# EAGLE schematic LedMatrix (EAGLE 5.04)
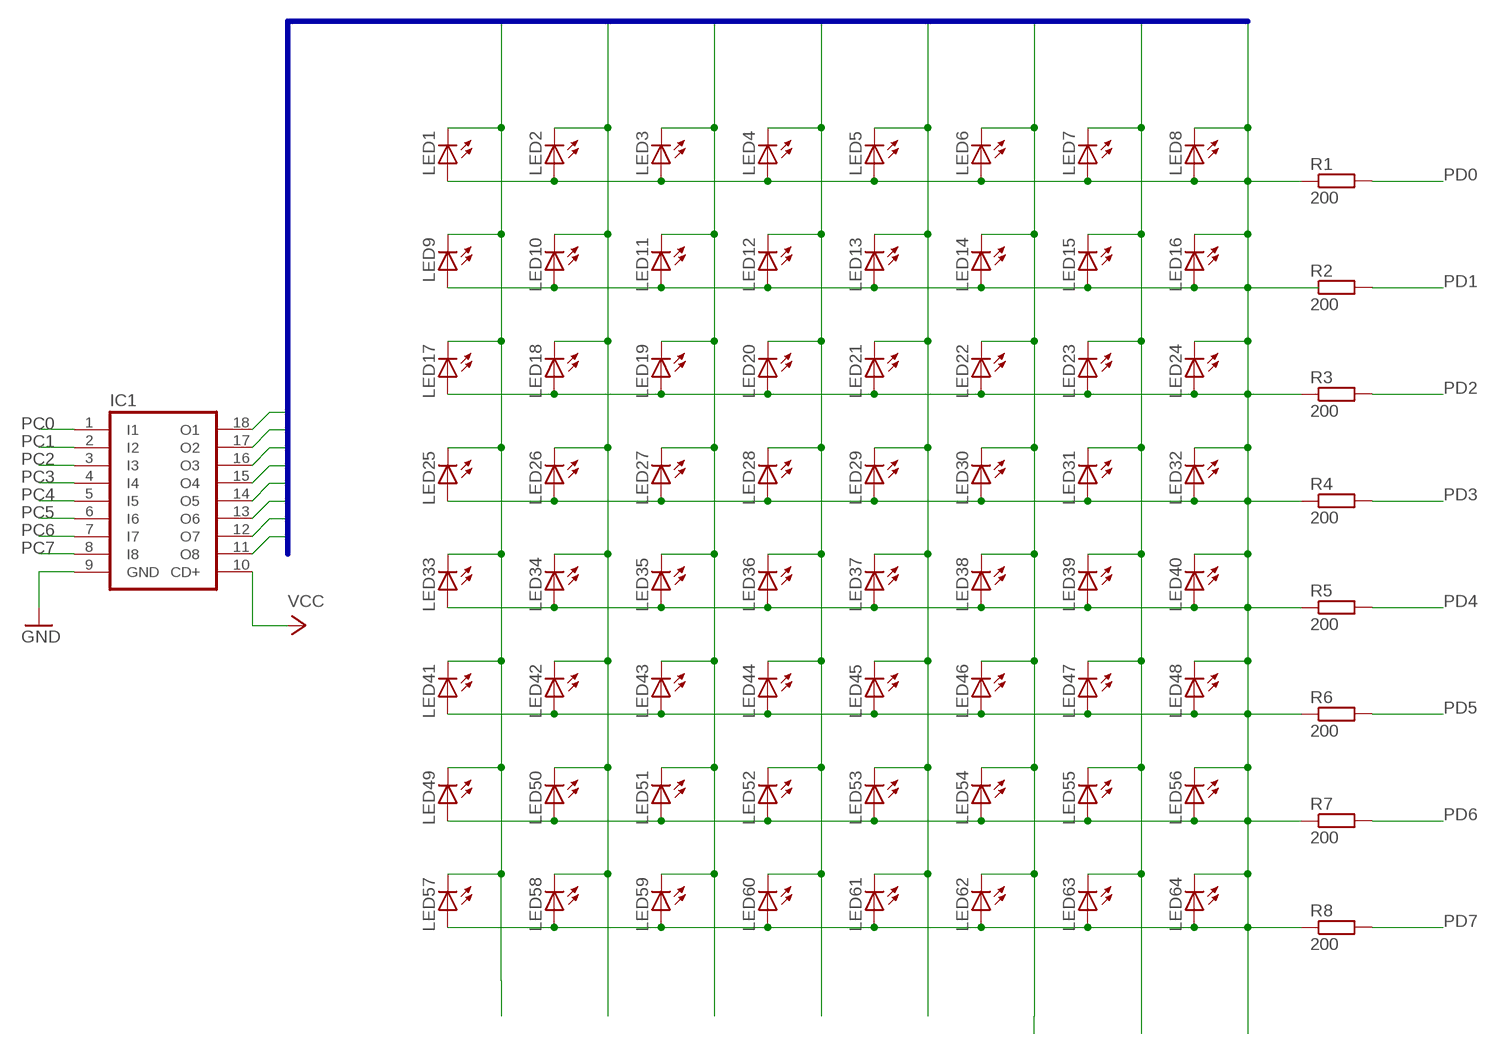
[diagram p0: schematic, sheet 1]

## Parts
IC1  ULN2804A  [DIL18]
LED1  LED  [SMARTLED-TTW]
LED2  LED  [SMARTLED-TTW]
LED3  LED  [SMARTLED-TTW]
LED4  LED  [SMARTLED-TTW]
LED5  LED  [SMARTLED-TTW]
LED6  LED  [SMARTLED-TTW]
LED7  LED  [SMARTLED-TTW]
LED8  LED  [SMARTLED-TTW]
LED9  LED  [SMARTLED-TTW]
LED10  LED  [SMARTLED-TTW]
LED11  LED  [SMARTLED-TTW]
LED12  LED  [SMARTLED-TTW]
LED13  LED  [SMARTLED-TTW]
LED14  LED  [SMARTLED-TTW]
LED15  LED  [SMARTLED-TTW]
LED16  LED  [SMARTLED-TTW]
LED17  LED  [SMARTLED-TTW]
LED18  LED  [SMARTLED-TTW]
LED19  LED  [SMARTLED-TTW]
LED20  LED  [SMARTLED-TTW]
LED21  LED  [SMARTLED-TTW]
LED22  LED  [SMARTLED-TTW]
LED23  LED  [SMARTLED-TTW]
LED24  LED  [SMARTLED-TTW]
LED25  LED  [SMARTLED-TTW]
LED26  LED  [SMARTLED-TTW]
LED27  LED  [SMARTLED-TTW]
LED28  LED  [SMARTLED-TTW]
LED29  LED  [SMARTLED-TTW]
LED30  LED  [SMARTLED-TTW]
LED31  LED  [SMARTLED-TTW]
LED32  LED  [SMARTLED-TTW]
LED33  LED  [SMARTLED-TTW]
LED34  LED  [SMARTLED-TTW]
LED35  LED  [SMARTLED-TTW]
LED36  LED  [SMARTLED-TTW]
LED37  LED  [SMARTLED-TTW]
LED38  LED  [SMARTLED-TTW]
LED39  LED  [SMARTLED-TTW]
LED40  LED  [SMARTLED-TTW]
LED41  LED  [SMARTLED-TTW]
LED42  LED  [SMARTLED-TTW]
LED43  LED  [SMARTLED-TTW]
LED44  LED  [SMARTLED-TTW]
LED45  LED  [SMARTLED-TTW]
LED46  LED  [SMARTLED-TTW]
LED47  LED  [SMARTLED-TTW]
LED48  LED  [SMARTLED-TTW]
LED49  LED  [SMARTLED-TTW]
LED50  LED  [SMARTLED-TTW]
LED51  LED  [SMARTLED-TTW]
LED52  LED  [SMARTLED-TTW]
LED53  LED  [SMARTLED-TTW]
LED54  LED  [SMARTLED-TTW]
LED55  LED  [SMARTLED-TTW]
LED56  LED  [SMARTLED-TTW]
LED57  LED  [SMARTLED-TTW]
LED58  LED  [SMARTLED-TTW]
LED59  LED  [SMARTLED-TTW]
LED60  LED  [SMARTLED-TTW]
LED61  LED  [SMARTLED-TTW]
LED62  LED  [SMARTLED-TTW]
LED63  LED  [SMARTLED-TTW]
LED64  LED  [SMARTLED-TTW]
R1  200  R-EU_0204/5  [0204/5]
R2  200  R-EU_0204/5  [0204/5]
R3  200  R-EU_0204/5  [0204/5]
R4  200  R-EU_0204/5  [0204/5]
R5  200  R-EU_0204/5  [0204/5]
R6  200  R-EU_0204/5  [0204/5]
R7  200  R-EU_0204/5  [0204/5]
R8  200  R-EU_0204/5  [0204/5]

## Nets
B$1: IC1.11(O8) IC1.12(O7) IC1.13(O6) IC1.14(O5) IC1.15(O4) IC1.16(O3) IC1.17(O2) IC1.18(O1) LED1.C@1(C) LED9.C@1(C) LED17.C@1(C) LED25.C@1(C)
GND: IC1.9(GND)
N$1: LED1.A@1(A) LED2.A@1(A) LED3.A@1(A) LED4.A@1(A) LED5.A@1(A) LED6.A@1(A) LED7.A@1(A) LED8.A@1(A) LED8.C@1(C) LED9.A@1(A) LED10.A@1(A) LED11.A@1(A) LED12.A@1(A) LED13.A@1(A) LED14.A@1(A) LED15.A@1(A) LED16.A@1(A) LED16.C@1(C) LED17.A@1(A) LED18.A@1(A) LED19.A@1(A) LED20.A@1(A) LED21.A@1(A) LED22.A@1(A) LED23.A@1(A) LED24.A@1(A) LED24.C@1(C) LED32.C@1(C) R1.1 R3.1
N$6: LED2.C@1(C) LED10.C@1(C) LED18.C@1(C) LED26.C@1(C)
N$7: LED3.C@1(C) LED11.C@1(C) LED19.C@1(C) LED27.C@1(C)
N$8: LED4.C@1(C) LED12.C@1(C) LED20.C@1(C) LED28.C@1(C)
N$9: LED5.C@1(C) LED13.C@1(C) LED21.C@1(C) LED29.C@1(C)
N$10: LED6.C@1(C) LED14.C@1(C) LED22.C@1(C) LED30.C@1(C)
N$11: LED7.C@1(C) LED15.C@1(C) LED23.C@1(C) LED31.C@1(C)
N$13: LED25.A@1(A) LED26.A@1(A) LED27.A@1(A) LED28.A@1(A) LED29.A@1(A) LED30.A@1(A) LED31.A@1(A) LED32.A@1(A) LED33.A@1(A) LED34.A@1(A) LED35.A@1(A) LED36.A@1(A) LED37.A@1(A) LED38.A@1(A) LED39.A@1(A) LED40.A@1(A) LED40.C@1(C) LED41.A@1(A) LED42.A@1(A) LED43.A@1(A) LED44.A@1(A) LED45.A@1(A) LED46.A@1(A) LED47.A@1(A) LED48.A@1(A) LED48.C@1(C) LED49.A@1(A) LED50.A@1(A) LED51.A@1(A) LED52.A@1(A) LED53.A@1(A) LED54.A@1(A) LED55.A@1(A) LED56.A@1(A) LED56.C@1(C) LED57.A@1(A) LED58.A@1(A) LED59.A@1(A) LED60.A@1(A) LED61.A@1(A) LED62.A@1(A) LED63.A@1(A) LED64.A@1(A) LED64.C@1(C) R4.1 R5.1 R6.1 R7.1 R8.1
N$16: LED33.C@1(C) LED41.C@1(C) LED49.C@1(C) LED57.C@1(C)
N$18: LED34.C@1(C) LED42.C@1(C) LED50.C@1(C) LED58.C@1(C)
N$19: LED35.C@1(C) LED43.C@1(C) LED51.C@1(C) LED59.C@1(C)
N$20: LED36.C@1(C) LED44.C@1(C) LED52.C@1(C) LED60.C@1(C)
N$21: LED37.C@1(C) LED45.C@1(C) LED53.C@1(C) LED61.C@1(C)
N$22: LED38.C@1(C) LED46.C@1(C) LED54.C@1(C) LED62.C@1(C)
N$23: LED39.C@1(C) LED47.C@1(C) LED55.C@1(C) LED63.C@1(C)
PC0: IC1.1(I1)
PC1: IC1.2(I2)
PC2: IC1.3(I3)
PC3: IC1.4(I4)
PC4: IC1.5(I5)
PC5: IC1.6(I6)
PC6: IC1.7(I7)
PC7: IC1.8(I8)
PD0: R1.2
PD1: R2.2
PD2: R3.2
PD3: R4.2
PD4: R5.2
PD5: R6.2
PD6: R7.2
PD7: R8.2
VCC: IC1.10(CD+)
Unconnected: R2.1

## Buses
B$1

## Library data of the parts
IC1 = uln-udn:ULN2804A: DRIVER ARRAY
LED1-LED64 = led:LED: LED
R1-R8 = rcl:R-EU_: RESISTOR, European symbol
